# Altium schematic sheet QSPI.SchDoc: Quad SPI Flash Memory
size A4; Date: 01-DEC-2013; Author: A.B; CompanyName: STMicroelectronics; Organization: Microcontrollers Division; Address1: 12, Rue Jules HOROWITZ; Address2: 38019 Grenoble; Address3: FRANCE; DocumentNumber: MB1184; Revision: C-01; SheetNumber: 9; SheetTotal: 10; Project: STM32L476G-DISCO
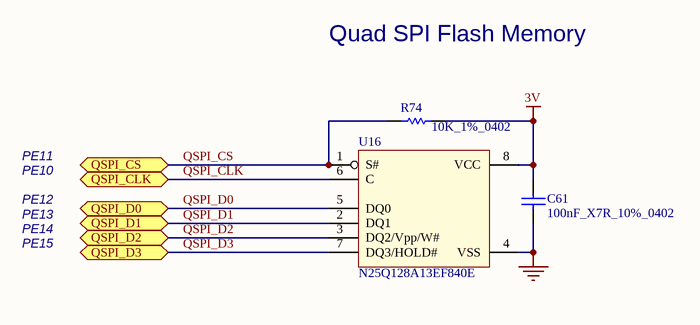
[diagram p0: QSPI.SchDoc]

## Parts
C61  100nF_X7R_10%_0402  [0402C]
R74  10K_1%_0402  [0402R]
U16  N25Q128A13EF840E  [V-PDFN-8 8x6]

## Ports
QSPI_CLK, QSPI_CS, QSPI_D0, QSPI_D1, QSPI_D2 (bidir), QSPI_D3

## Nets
3V: C61.2 R74.2 U16.8(VCC)
GND: C61.1 U16.4(VSS)
QSPI_CLK: U16.6(C) ; port QSPI_CLK
QSPI_CS: R74.1 U16.1(S#) ; port QSPI_CS
QSPI_D0: U16.5(DQ0) ; port QSPI_D0
QSPI_D1: U16.2(DQ1) ; port QSPI_D1
QSPI_D2: U16.3(DQ2/Vpp/W#) ; port QSPI_D2
QSPI_D3: U16.7(DQ3/HOLD#) ; port QSPI_D3

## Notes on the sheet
- Quad SPI Flash Memory
- PE10
- PE11
- PE12
- PE13
- PE14
- PE15

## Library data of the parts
C61 = Cap_100nF_X7R_10%_0402: Capacitor,100nF,16V,X7R,10%,0402,YAGEO; Manuf_Part_1: CC0402KRX7R7BB104
R74 = Res_10K_1%_0402: Resistor,10K,0402,1%,YAGEO; Manuf_Part_1: RC0402FR-0710KL
U16 = N25Q128A13EF840E: 128Mb, 3V, Multiple I/O Serial Flash Memory, Quad/Dual; Manuf_1: MICRON; Manuf_Part_2: N25Q256A13EF840E; Manuf_Part_3: N25Q512A13EF840E; ECCN_US/EU: 3A991/NEC; Order: N25Q128A13EF840F-ND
